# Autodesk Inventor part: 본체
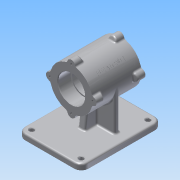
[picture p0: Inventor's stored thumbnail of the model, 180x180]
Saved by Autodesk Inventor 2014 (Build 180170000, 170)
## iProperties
Created: 2015-12
Part Number: 본체
Material: 알루미늄 6061
Document SubType Name: Modeling
Designer: Owner
Density: 2.71 g/cm^3
Appearance: 알루미늄 - 평지
Mass: 1165.38 g
Surface Area: 815.057 cm^2
Volume: 430.029 cm^3
Author: Owner
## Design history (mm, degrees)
sketch "스케치1"
  geometry: L1 (-42.5, 0)-(42.5, 0); L2 (-42.5, 0)-(-42.5, 37); L3 (-42.5, 37)-(42.5, 37); L4 (42.5, 37)-(42.5, 0); L5 (-42.5, 23.5)-(-20.5, 23.5); L6 (-20.5, 23.5)-(-20.5, 21); L7 (-20.5, 21)-(20.5, 21); L8 (20.5, 21)-(20.5, 23.5); L9 (20.5, 23.5)-(42.5, 23.5); 2 further points
  constraints: 18 end point, 4 perpendicular, 2 horizontal, 2 point on line, 2 vertical, 1 coincident, 1 horizontal alignment, 1 midpoint, 1 parallel
  dimensions: "d0" = 74 diameter of L3 L1; "d1" = 85 distance of L2.end L3.end; "d2" = 47 diameter of L5 L1; "d3" = 42 diameter of L7 L1; "d4" = 47 diameter of L9 L1 (derived); "d5" = 22 distance of L5.start L5.end; "d6" = 41 distance of L6.end L7.end; "d7" = 22 distance of L8.end L9.end (derived)
revolve "회전1" sketch "스케치1" stored, may be unused: angle "d8" = 90 deg
sketch "스케치2"
  geometry: C1 r 23.5 at (0, 0) reference; C2 r 7 at (37, 0); 1 further point
  constraints: 2 horizontal alignment, 1 centre point, 1 other
  dimensions: "d9" = 14 diameter of C2
extrude "돌출1" join sketch "스케치2" distance "d10" = 15; taper "d11" = 0 deg
sketch "스케치3"
  geometry: L1 (27.5, 44)-(27.5, 36.338) reference; L2 (27.5, 37)-(-42.5, 37) reference; L3 (27.5, 37)-(30.048, 44); L4 (42.5, 44)-(27.5, 44) reference; L5 (42.5, 23.5)-(42.5, -23.5) reference; L6 (-42.5, 23.5)-(-42.5, -23.5) reference; L7 (42.5, 0)-(-42.5, 0); 1 further point
  constraints: 4 end point, 2 midpoint, 1 point on line
  dimensions: "d12" = 110 deg angle of L3 L2
revolve "회전2" sketch "스케치3" stored, may be unused: angle "d13" = 90 deg
sketch "스케치4"
  geometry: A1 r 7 centre (0, 0) between (-0.662, -6.969) and (-0.662, 6.969) reference
hole "구멍1" sketch "스케치4" at (0, 0) diameter "d14" = 3.242; stored, may be unused: countersink angle "d18" = 90 deg, drill point angle "d20" = 118 deg; dims "d15" = 9, "d16" = 4, "d17" = 2, "d19" = 11
node "작업 평면1"
sketch "스케치6"
  geometry: L1 (-80, 55)-(60, 55); L2 (60, 55)-(60, -55); L3 (60, -55)-(-80, -55); L4 (-80, -55)-(-80, 55); L5 (-42.5, -7)-(-42.5, 7) reference; L6 (-42.5, 6.969)-(-42.5, 36.338) reference; 4 further points
  constraints: 8 end point, 2 midpoint, 2 parallel, 1 horizontal, 1 horizontal alignment, 1 perpendicular
  dimensions: "d26" = 37.5 distance between parallel lines of L6 L4; "d27" = 140 distance of L1.start L1.end; "d28" = 110 distance of L1.end L2.end
extrude "돌출2" join sketch "스케치6" distance "d29" = 10; taper "d30" = 0 deg
sketch "스케치7"
  geometry: L1 (-80, 55)-(-80, -55) reference; L2 (-4, 37)-(4, 37); L3 (4, 37)-(4, -37); L4 (4, -37)-(-4, -37); L5 (-4, -37)-(-4, 37); L6 (-27.5, 37)-(27.5, 37) reference; L7 (-27.5, -37)-(27.5, -37) reference; 2 further points
  constraints: 8 end point, 2 horizontal alignment, 2 parallel, 1 horizontal, 1 midpoint, 1 perpendicular, 1 vertical alignment
  dimensions: "d31" = 80 distance from line of point (0, 37) L1 (derived); "d32" = 8 distance between parallel lines of L3 L5; "d33" = 76 distance between parallel lines of L5 L1 (derived)
extrude "돌출3" join sketch "스케치7" stored distance "d34" = 10; taper "d35" = 0 deg
sketch "스케치8"
  geometry: L1 (27.5, -37)-(-27.5, -37) reference; L2 (-60, -70)-(80, -70) reference; L3 (20.948, -37)-(25, -70); L4 (-20.948, -37)-(-25, -70); L5 (-4, -70)-(-4, 0) reference; L6 (4, 0)-(-4, 0) reference; L7 (-4, -70)-(-4, 0) reference; L8 (4, -70)-(-4, -70) reference; L9 (4, -70)-(4, 0) reference; 2 further points
  constraints: 4 end point, 4 point on line, 1 midpoint
  dimensions: "d36" = 97 deg angle of L2 L3; "d37" = 97 deg angle of L2 L4; "d38" = 25 distance of point (0, -70) L3.end; "d39" = 25 distance of L4.end point (0, -70); "d40" = 50 distance of L4.end L3.end (derived)
  node "투영된 루프1"
feature "리브1" dims "d41" = 1, "d42" = 12, "d43" = 0, "d44" = 0, "d45" = 1, "d46" = 1
feature "리브2" dims "d47" = 1, "d48" = 12, "d49" = 0, "d50" = 0, "d51" = 1, "d52" = 1
sketch "스케치10"
  geometry: L1 (60, -55)-(60, 55) reference; L2 (60, 55)-(-80, 55) reference; L3 (-80, 55)-(-80, -55) reference; L4 (-80, -55)-(60, -55) reference; 5 further points
  constraints: 2 horizontal alignment, 2 vertical alignment
  dimensions: "d53" = 12 distance from line of point (-68, 43) L3; "d54" = 12 distance from line of point (-68, 43) L2; "d55" = 12 distance from line of L2 point (48, 43) (derived); "d56" = 12 distance from line of point (48, 43) L1; "d57" = 12 distance from line of L4 point (48, -43)
hole "구멍2" sketch "스케치10" at (-68, 43), (48, 43), (48, -43), (-68, -43) diameter "d58" = 8; stored, may be unused: countersink angle "d62" = 90 deg, drill point angle "d64" = 118 deg; dims "d59" = 9, "d60" = 4, "d61" = 2, "d63" = 11
fillet "모깎기1" dims "d65" = 0.3
fillet "모깎기2" dims "d66" = 12, "d67" = 3
fillet "모깎기3" dims "d68" = 3
fillet "모깎기4" dims "d69" = 3
node "작업 평면3"
  node "작업 평면2"
sketch "스케치11"
  geometry: 2 further points
  constraints: 1 coincident, 1 other
feature "엠보싱1" sketch "스케치11" dims "d0" = 74, "d1" = 85, "d2" = 47, "d3" = 42, "d4" = 47 (derived), "d5" = 22, "d6" = 41, "d7" = 22 (derived), "d11" = 0, "d71" = 0.5, "d72" = 0
chamfer "모따기1" distance "d73" = 1; stored, may be unused: second distance "d74" = 2, angle "d75" = 45 deg
node "솔리드1"
pattern_circular "원형 패턴1" dims "d22" = 360 deg
mirror "대칭1"
other parameters: "d70" = 135 deg
